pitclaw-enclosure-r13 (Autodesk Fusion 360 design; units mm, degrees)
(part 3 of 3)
sketch "Uniform locating lip outer corner clearance profile" plane through (0, 0, 0) normal (0, 0, 1) x axis (1, 0, 0)
  line L1 (-40.2, -49.2) -> (-38, -49.2)
  line L2 (-40.2, -47) -> (-40.2, -49.2)
  line L3 (-40.2, 49.2) -> (-38, 49.2)
  line L4 (-40.2, 47) -> (-40.2, 49.2)
  line L5 (40.2, -49.2) -> (38, -49.2)
  line L6 (40.2, -47) -> (40.2, -49.2)
  line L7 (40.2, 49.2) -> (38, 49.2)
  line L8 (40.2, 47) -> (40.2, 49.2)
  arc A1 centre (-38, -47) radius 2.2 clockwise from (-38, -49.2) to (-40.2, -47)
  arc A2 centre (-38, 47) radius 2.2 clockwise from (-40.2, 47) to (-38, 49.2)
  arc A3 centre (38, -47) radius 2.2 clockwise from (40.2, -47) to (38, -49.2)
  arc A4 centre (38, 47) radius 2.2 clockwise from (38, 49.2) to (40.2, 47)
extrude "Extrude19" cut sketch "Uniform locating lip outer corner clearance profile" blind 2 from offset 25.6
sketch "Insulating floor profile" plane through (0, 0, 0) normal (0, 0, 1) x axis (1, 0, 0)
  line L1 (-6.88, 25.362) -> (-22.12, 25.362)
  line L2 (-4.34, 46.317) -> (-4.34, 27.902)
  line L3 (-22.12, 48.857) -> (-6.88, 48.857)
  line L4 (-24.66, 27.902) -> (-24.66, 46.317)
  arc A1 centre (-6.88, 27.902) radius 2.54 clockwise from (-4.34, 27.902) to (-6.88, 25.362)
  arc A2 centre (-6.88, 46.317) radius 2.54 clockwise from (-6.88, 48.857) to (-4.34, 46.317)
  arc A3 centre (-22.12, 46.317) radius 2.54 clockwise from (-24.66, 46.317) to (-22.12, 48.857)
  arc A4 centre (-22.12, 27.902) radius 2.54 clockwise from (-22.12, 25.362) to (-24.66, 27.902)
extrude "Extrude1" new body sketch "Insulating floor profile" blind 0.8 from offset 9.1 bodies "Adafruit5807 printed base spacer"
sketch "Rear bearing blank profile" plane through (0, 0, 0) normal (0, 0, 1) x axis (1, 0, 0)
  line L1 (-6.88, 25.362) -> (-22.12, 25.362)
  line L2 (-4.34, 46.317) -> (-4.34, 27.902)
  line L3 (-22.12, 48.857) -> (-6.88, 48.857)
  line L4 (-24.66, 27.902) -> (-24.66, 46.317)
  arc A1 centre (-6.88, 27.902) radius 2.54 clockwise from (-4.34, 27.902) to (-6.88, 25.362)
  arc A2 centre (-6.88, 46.317) radius 2.54 clockwise from (-6.88, 48.857) to (-4.34, 46.317)
  arc A3 centre (-22.12, 46.317) radius 2.54 clockwise from (-24.66, 46.317) to (-22.12, 48.857)
  arc A4 centre (-22.12, 27.902) radius 2.54 clockwise from (-22.12, 25.362) to (-24.66, 27.902)
extrude "Extrude2" new body sketch "Rear bearing blank profile" blind 3 from offset 9.1
sketch "Rear edge bearing strip profile" plane through (0, 0, 0) normal (0, 0, 1) x axis (1, 0, 0)
  line L1 (-3.34, 25.362) -> (-25.66, 25.362)
  line L2 (-3.34, 26.462) -> (-3.34, 25.362)
  line L3 (-25.66, 26.462) -> (-3.34, 26.462)
  line L4 (-25.66, 25.362) -> (-25.66, 26.462)
extrude "Extrude3" sketch "Rear edge bearing strip profile" blind 6 from offset 8.1
combine "Combine1"
sketch "Side and front bearing frame profile" plane through (0, 0, 0) normal (0, 0, 1) x axis (1, 0, 0)
  line L1 (-6.88, 23.862) -> (-22.12, 23.862)
  line L2 (-2.84, 46.317) -> (-2.84, 27.902)
  line L3 (-22.12, 50.357) -> (-6.88, 50.357)
  line L4 (-26.16, 27.902) -> (-26.16, 46.317)
  line L5 (-6.88, 26.862) -> (-22.12, 26.862)
  line L6 (-5.84, 46.317) -> (-5.84, 27.902)
  line L7 (-22.12, 47.357) -> (-6.88, 47.357)
  line L8 (-23.16, 27.902) -> (-23.16, 46.317)
  arc A1 centre (-6.88, 27.902) radius 4.04 clockwise from (-2.84, 27.902) to (-6.88, 23.862)
  arc A2 centre (-6.88, 46.317) radius 4.04 clockwise from (-6.88, 50.357) to (-2.84, 46.317)
  arc A3 centre (-22.12, 46.317) radius 4.04 clockwise from (-26.16, 46.317) to (-22.12, 50.357)
  arc A4 centre (-22.12, 27.902) radius 4.04 clockwise from (-22.12, 23.862) to (-26.16, 27.902)
  arc A5 centre (-6.88, 27.902) radius 1.04 clockwise from (-5.84, 27.902) to (-6.88, 26.862)
  arc A6 centre (-6.88, 46.317) radius 1.04 clockwise from (-6.88, 47.357) to (-5.84, 46.317)
  arc A7 centre (-22.12, 46.317) radius 1.04 clockwise from (-23.16, 46.317) to (-22.12, 47.357)
  arc A8 centre (-22.12, 27.902) radius 1.04 clockwise from (-22.12, 26.862) to (-23.16, 27.902)
extrude "Extrude4" new body sketch "Side and front bearing frame profile" blind 3 from offset 9.1
sketch "Side and front bearing frame ends clear profile" plane through (0, 0, 0) normal (0, 0, 1) x axis (1, 0, 0)
  line L1 (0.66, 26.262) -> (-30.34, 26.262)
  line L2 (0.66, 48.162) -> (0.66, 26.262)
  line L3 (-30.34, 48.162) -> (0.66, 48.162)
  line L4 (-30.34, 26.262) -> (-30.34, 48.162)
extrude "Extrude5" sketch "Side and front bearing frame ends clear profile" blind 7 from offset 8.1
combine "Combine2"
sketch "Side and curved front locating lips profile" plane through (0, 0, 0) normal (0, 0, 1) x axis (1, 0, 0)
  line L1 (-6.88, 23.862) -> (-22.12, 23.862)
  line L2 (-2.84, 46.317) -> (-2.84, 27.902)
  line L3 (-22.12, 50.357) -> (-6.88, 50.357)
  line L4 (-26.16, 27.902) -> (-26.16, 46.317)
  line L5 (-6.88, 25.062) -> (-22.12, 25.062)
  line L6 (-4.04, 46.317) -> (-4.04, 27.902)
  line L7 (-22.12, 49.157) -> (-6.88, 49.157)
  line L8 (-24.96, 27.902) -> (-24.96, 46.317)
  arc A1 centre (-6.88, 27.902) radius 4.04 clockwise from (-2.84, 27.902) to (-6.88, 23.862)
  arc A2 centre (-6.88, 46.317) radius 4.04 clockwise from (-6.88, 50.357) to (-2.84, 46.317)
  arc A3 centre (-22.12, 46.317) radius 4.04 clockwise from (-26.16, 46.317) to (-22.12, 50.357)
  arc A4 centre (-22.12, 27.902) radius 4.04 clockwise from (-22.12, 23.862) to (-26.16, 27.902)
  arc A5 centre (-6.88, 27.902) radius 2.84 clockwise from (-4.04, 27.902) to (-6.88, 25.062)
  arc A6 centre (-6.88, 46.317) radius 2.84 clockwise from (-6.88, 49.157) to (-4.04, 46.317)
  arc A7 centre (-22.12, 46.317) radius 2.84 clockwise from (-24.96, 46.317) to (-22.12, 49.157)
  arc A8 centre (-22.12, 27.902) radius 2.84 clockwise from (-22.12, 25.062) to (-24.96, 27.902)
extrude "Extrude6" new body sketch "Side and curved front locating lips profile" blind 1.2 from offset 12.1
sketch "Side and curved front locating lips ends clear profile" plane through (0, 0, 0) normal (0, 0, 1) x axis (1, 0, 0)
  line L1 (0.66, 31.562) -> (-30.34, 31.562)
  line L2 (0.66, 48.162) -> (0.66, 31.562)
  line L3 (-30.34, 48.162) -> (0.66, 48.162)
  line L4 (-30.34, 31.562) -> (-30.34, 48.162)
extrude "Extrude7" sketch "Side and curved front locating lips ends clear profile" blind 7 from offset 8.1
combine "Combine3"
sketch "M2 compression pads profile" plane through (0, 0, 0) normal (0, 0, 1) x axis (1, 0, 0)
  circle C1 centre (-6.753, 46.317) radius 2.5
  circle C2 centre (-21.993, 46.317) radius 2.5
extrude "Extrude8" add sketch "M2 compression pads profile" blind 3 from offset 9.1
sketch "Rear stop support 6.2 profile" plane through (0, 0, 0) normal (0, 0, 1) x axis (1, 0, 0)
  line L1 (-10.54, 23.862) -> (-12.14, 23.862)
  line L2 (-10.54, 26.462) -> (-10.54, 23.862)
  line L3 (-12.14, 26.462) -> (-10.54, 26.462)
  line L4 (-12.14, 23.862) -> (-12.14, 26.462)
extrude "Extrude9" add sketch "Rear stop support 6.2 profile" blind 3 from offset 9.1
sketch "Rear stop 6.2 profile" plane through (0, 0, 0) normal (0, 0, 1) x axis (1, 0, 0)
  line L1 (-10.54, 23.862) -> (-12.14, 23.862)
  line L2 (-10.54, 25.062) -> (-10.54, 23.862)
  line L3 (-12.14, 25.062) -> (-10.54, 25.062)
  line L4 (-12.14, 23.862) -> (-12.14, 25.062)
extrude "Extrude10" add sketch "Rear stop 6.2 profile" blind 1.2 from offset 12.1
sketch "Rear stop support 12.9 profile" plane through (0, 0, 0) normal (0, 0, 1) x axis (1, 0, 0)
  line L1 (-17.24, 23.862) -> (-18.84, 23.862)
  line L2 (-17.24, 26.462) -> (-17.24, 23.862)
  line L3 (-18.84, 26.462) -> (-17.24, 26.462)
  line L4 (-18.84, 23.862) -> (-18.84, 26.462)
extrude "Extrude11" add sketch "Rear stop support 12.9 profile" blind 3 from offset 9.1
sketch "Rear stop 12.9 profile" plane through (0, 0, 0) normal (0, 0, 1) x axis (1, 0, 0)
  line L1 (-17.24, 23.862) -> (-18.84, 23.862)
  line L2 (-17.24, 25.062) -> (-17.24, 23.862)
  line L3 (-18.84, 25.062) -> (-17.24, 25.062)
  line L4 (-18.84, 23.862) -> (-18.84, 25.062)
extrude "Extrude12" add sketch "Rear stop 12.9 profile" blind 1.2 from offset 12.1
sketch "Output solder and wire relief profile" plane through (0, 0, 0) normal (0, 0, 1) x axis (1, 0, 0)
  line L1 (-5.44, 26.662) -> (-23.56, 26.662)
  line L2 (-5.14, 31.362) -> (-5.14, 26.962)
  line L3 (-23.56, 31.662) -> (-5.44, 31.662)
  line L4 (-23.86, 26.962) -> (-23.86, 31.362)
  arc A1 centre (-5.44, 26.962) radius 0.3 clockwise from (-5.14, 26.962) to (-5.44, 26.662)
  arc A2 centre (-5.44, 31.362) radius 0.3 clockwise from (-5.44, 31.662) to (-5.14, 31.362)
  arc A3 centre (-23.56, 31.362) radius 0.3 clockwise from (-23.86, 31.362) to (-23.56, 31.662)
  arc A4 centre (-23.56, 26.962) radius 0.3 clockwise from (-23.56, 26.662) to (-23.86, 26.962)
extrude "Extrude13" cut sketch "Output solder and wire relief profile" blind 4.31 from offset 9.09
sketch "USB solder and peg relief 4.84 profile" plane through (0, 0, 0) normal (0, 0, 1) x axis (1, 0, 0)
  line L1 (-9.48, 41.662) -> (-12.035, 41.662)
  line L2 (-9.18, 49.062) -> (-9.18, 41.962)
  line L3 (-12.035, 49.362) -> (-9.48, 49.362)
  line L4 (-12.335, 41.962) -> (-12.335, 49.062)
  arc A1 centre (-9.48, 41.962) radius 0.3 clockwise from (-9.18, 41.962) to (-9.48, 41.662)
  arc A2 centre (-9.48, 49.062) radius 0.3 clockwise from (-9.48, 49.362) to (-9.18, 49.062)
  arc A3 centre (-12.035, 49.062) radius 0.3 clockwise from (-12.335, 49.062) to (-12.035, 49.362)
  arc A4 centre (-12.035, 41.962) radius 0.3 clockwise from (-12.035, 41.662) to (-12.335, 41.962)
extrude "Extrude14" cut sketch "USB solder and peg relief 4.84 profile" blind 4.31 from offset 9.09
sketch "USB solder and peg relief 12.325 profile" plane through (0, 0, 0) normal (0, 0, 1) x axis (1, 0, 0)
  line L1 (-16.965, 41.662) -> (-19.52, 41.662)
  line L2 (-16.665, 49.062) -> (-16.665, 41.962)
  line L3 (-19.52, 49.362) -> (-16.965, 49.362)
  line L4 (-19.82, 41.962) -> (-19.82, 49.062)
  arc A1 centre (-16.965, 41.962) radius 0.3 clockwise from (-16.665, 41.962) to (-16.965, 41.662)
  arc A2 centre (-16.965, 49.062) radius 0.3 clockwise from (-16.965, 49.362) to (-16.665, 49.062)
  arc A3 centre (-19.52, 49.062) radius 0.3 clockwise from (-19.82, 49.062) to (-19.52, 49.362)
  arc A4 centre (-19.52, 41.962) radius 0.3 clockwise from (-19.52, 41.662) to (-19.82, 41.962)
extrude "Extrude15" cut sketch "USB solder and peg relief 12.325 profile" blind 4.31 from offset 9.09
sketch "M2 screw clearance profile" plane through (0, 0, 0) normal (0, 0, 1) x axis (1, 0, 0)
  circle C1 centre (-6.753, 46.317) radius 1.2
  circle C2 centre (-21.993, 46.317) radius 1.2
extrude "Extrude16" cut sketch "M2 screw clearance profile" blind 4.31 from offset 9.09
sketch "Published PCB corner trim profile" plane through (0, 0, 0) normal (0, 0, 1) x axis (1, 0, 0)
  line L1 (-24.66, 25.362) -> (-22.12, 25.362)
  line L2 (-24.66, 27.902) -> (-24.66, 25.362)
  line L3 (-24.66, 48.857) -> (-22.12, 48.857)
  line L4 (-24.66, 46.317) -> (-24.66, 48.857)
  line L5 (-4.34, 25.362) -> (-6.88, 25.362)
  line L6 (-4.34, 27.902) -> (-4.34, 25.362)
  line L7 (-4.34, 48.857) -> (-6.88, 48.857)
  line L8 (-4.34, 46.317) -> (-4.34, 48.857)
  arc A1 centre (-22.12, 27.902) radius 2.54 clockwise from (-22.12, 25.362) to (-24.66, 27.902)
  arc A2 centre (-22.12, 46.317) radius 2.54 clockwise from (-24.66, 46.317) to (-22.12, 48.857)
  arc A3 centre (-6.88, 27.902) radius 2.54 clockwise from (-4.34, 27.902) to (-6.88, 25.362)
  arc A4 centre (-6.88, 46.317) radius 2.54 clockwise from (-6.88, 48.857) to (-4.34, 46.317)
extrude "Extrude12" cut sketch "Published PCB corner trim profile" blind 1.62 from offset 12.09
remove_body "RemoveBody1"
remove_body "RemoveBody2"
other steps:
base_feature "Base Feature1" bodies "Bottom shell - corrected physical connector order", "04 Probe fascia - fitted seams"
create_component "CreateComponent1"
create_component "CreateComponent2"
create_component "CreateComponent3"
create_component "CreateComponent4"
create_component "CreateComponent5"
create_component "CreateComponent6"
create_component "CreateComponent1"
create_component "CreateComponent1"
create_component "CreateComponent2"
create_component "CreateComponent3"
create_component "CreateComponent4"
create_component "CreateComponent5"
create_component "CreateComponent6"
create_component "CreateComponent7"
create_component "CreateComponent8"
create_component "CreateComponent9"
create_component "CreateComponent10"
create_component "CreateComponent11"
create_component "CreateComponent12"
create_component "CreateComponent13"
create_component "CreateComponent7"
create_component "CreateComponent1"
create_component "CreateComponent2"
create_component "CreateComponent3"
create_component "CreateComponent4"
create_component "CreateComponent5"
create_component "CreateComponent6"
create_component "CreateComponent7"
create_component "CreateComponent8"
create_component "CreateComponent9"
create_component "CreateComponent10"
create_component "CreateComponent11"
create_component "CreateComponent12"
create_component "CreateComponent13"
create_component "CreateComponent14"
create_component "CreateComponent15"
create_component "CreateComponent16"
create_component "CreateComponent17"
create_component "CreateComponent18"
create_component "CreateComponent8"
create_component "CreateComponent9"
create_component "CreateComponent10"
named bodies: "01 Bottom shell", "02 Top bezel - fitted lip and 4.2mm pilots", "03 WT32 retainer - four anchors", "Carrier PCB - placed components omitted", "WT32 nominal envelope - sample verification required", "01 Bottom shell - fitted guides and 4.2mm pilots", "C1 electrolytic sleeve", "C1 aluminum top", "C1 leads", "C1 leads (1)", "C3 electrolytic sleeve", "C3 aluminum top", "C3 leads", "C3 leads (1)", "C2 ceramic body", "C2 leads", "C2 leads (1)", "C4 ceramic body", "C4 leads", "C4 leads (1)", "C10 ceramic body", "C10 leads", "C10 leads (1)", "C11 ceramic body", "C11 leads", "C11 leads (1)", "C12 ceramic body", "C12 leads", "C12 leads (1)", "K1 relay case", "K1 leads", "K1 leads (1)", "K1 leads (2)", "K1 leads (3)", "K1 leads (4)", "U2 converter case", "U2 leads", "U2 leads (1)", "U2 leads (2)", "Q1 insulating support", "Q1 metal tab", "Q1 molded body", "Q1 bent lead 1", "Q1 lead tail 1", "Q1 bent lead 2", "Q1 lead tail 2", "Q1 bent lead 3", "Q1 lead tail 3", "BZ1 piezo housing", "BZ1 leads", "BZ1 leads (1)", "J2 RJ45 housing", "J2 contact 1", "J2 contact 2", "J2 contact 3", "J2 contact 4", "J2 contact 5", "J2 contact 6", "J2 contact 7", "J2 contact 8"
